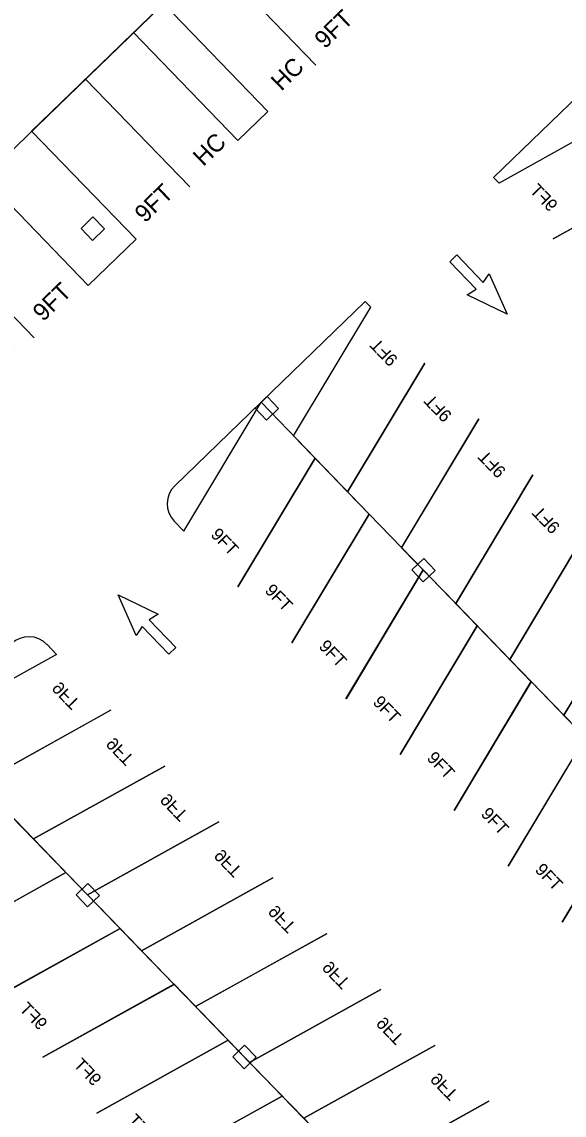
# Model space of a CAD drawing. Extents: x 468143 to 491361, y 1438528 to 1468730.
# Drawn here: x 490229.7 to 490294.7, y 1467411.7 to 1467542.8 of the extents above; entities that cross this region are included whole.
import ezdxf

# ---------------------------------------------------------------- set-up
doc = ezdxf.new("R2010")
doc.units = 0
doc.layers.add('Default', color=7, linetype='Continuous')
doc.layers.add('Xreference_dp', color=7, linetype='Continuous')

# ---------------------------------------------------------------- blocks, each defined once
blk = doc.blocks.new('STALL 9FT-75D')
at = {"layer": 'Default'}
for p, q in [((0, 0), (111.8, 0)), ((111.8, 0), (167.7, -208.6))]:
    blk.add_line(p, q, dxfattribs=at)
blk.add_lwpolyline([(55.9, -208.6), (0, 0)], dxfattribs=at)
blk.add_text('9FT', height=18, dxfattribs=at).set_placement((86.4, -185.9))
blk = doc.blocks.new('arrow-thru')
at = {"layer": 'Default'}
blk.add_lwpolyline([(14.99997, 0), (28.999942, 0), (28.999942, 54.99989), (43.999912, 51.999896), (21.999956, 111.999776), (0, 51.999896), (14.99997, 54.99989)], close=True, dxfattribs=at)
blk = doc.blocks.new('STALL 9FT')
at = {"layer": 'Default'}
for points in [[(0, 0), (0, 216)], [(108, 216), (108, 0)]]:
    blk.add_lwpolyline(points, dxfattribs=at)
blk.add_text('9FT', height=25, dxfattribs=at).set_placement((24.7, 7.1))
blk = doc.blocks.new('STALL HC')
at = {"layer": 'Default'}
blk.add_lwpolyline([(0, 0), (0, 216), (96, 216), (96, 0)], dxfattribs=at)
blk.add_text('HC', height=25, dxfattribs=at).set_placement((33.6, 7.1))
blk = doc.blocks.new('Col 24x24')
at = {"layer": 'Default'}
blk.add_lwpolyline([(-11.999976, -11.999976), (-11.999976, 11.999976), (11.999976, 11.999976), (11.999976, -11.999976), (-11.999976, -11.999976)], dxfattribs=at)
blk.add_lwpolyline([(-11.999976, -11.999976), (11.999976, -11.999976), (11.999976, 11.999976), (-11.999976, 11.999976)], close=True, dxfattribs=at)

msp = doc.modelspace()

# ---------------------------------------------------------------- linework, layer by layer
at = {"layer": 'Xreference_dp'}
for p, q in [((490265.37, 1467563.03), (490230.88, 1467529.65)), ((490265.37, 1467563.03), (490230.88, 1467529.65)), ((490298.74, 1467536.2), (490286.25, 1467524.11)), ((490298.74, 1467536.2), (490286.25, 1467524.11)), ((490255.61, 1467528.54), (490259.2, 1467532.01)), ((490255.61, 1467528.54), (490259.2, 1467532.01)), ((490286.91, 1467523.43), (490286.25, 1467524.11)), ((490286.91, 1467523.43), (490286.25, 1467524.11)), ((490237.64, 1467511.15), (490243.39, 1467516.71)), ((490237.64, 1467511.15), (490243.39, 1467516.71)), ((490258.38, 1467497.15), (490270.87, 1467509.24)), ((490258.38, 1467497.15), (490270.87, 1467509.24)), ((490271.53, 1467508.56), (490270.87, 1467509.24)), ((490271.53, 1467508.56), (490270.87, 1467509.24))]:
    msp.add_line(p, q, dxfattribs=at)
for points in [[(490163.78, 1467464.71), (490266.02, 1467563.64), (490277.14, 1467552.15), (490385.5, 1467657)], [(490163.78, 1467464.71), (490266.02, 1467563.64), (490277.14, 1467552.15), (490385.5, 1467657)], [(490248.04, 1467487.14), (490258.38, 1467497.15)], [(490248.04, 1467487.14), (490258.38, 1467497.15)], [(490249.12, 1467481.71), (490247.97, 1467482.9)], [(490249.12, 1467481.71), (490247.97, 1467482.9)], [(490233.87, 1467466.94), (490232.72, 1467468.14)], [(490233.87, 1467466.94), (490232.72, 1467468.14)]]:
    msp.add_lwpolyline(points, dxfattribs=at)
for centre, start, end in [((490250.12, 1467484.99), 134.0571, 224.0571), ((490250.12, 1467484.99), 134.0571, 224.0571), ((490230.56, 1467466.05), 44.0571, 134.0571), ((490230.56, 1467466.05), 44.0571, 134.0571)]:
    msp.add_arc(centre, 3, start, end, dxfattribs=at)

# ---------------------------------------------------------------- block references
for name, p, xscale, yscale, rotation in [('STALL 9FT', (490264.95, 1467537.58), 0.0833307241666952, 0.08333072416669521, 44.05706724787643), ('STALL 9FT', (490264.95, 1467537.58), 0.0833307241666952, 0.08333072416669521, 44.05706724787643), ('STALL HC', (490259.2, 1467532.01), 0.08333072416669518, 0.0833307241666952, 44.069997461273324), ('STALL HC', (490259.2, 1467532.01), 0.08333072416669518, 0.0833307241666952, 44.069997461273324), ('STALL HC', (490249.86, 1467522.97), 0.08333072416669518, 0.0833307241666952, 44.069997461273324), ('STALL HC', (490249.86, 1467522.97), 0.08333072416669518, 0.0833307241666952, 44.069997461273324), ('STALL 9FT', (490243.39, 1467516.71), 0.0833307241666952, 0.08333072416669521, 44.05706724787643), ('STALL 9FT', (490243.39, 1467516.71), 0.0833307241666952, 0.08333072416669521, 44.05706724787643), ('STALL 9FT-75D', (490309.12, 1467525.48), 0.08333072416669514, -0.08333072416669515, 134.0570672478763), ('STALL 9FT-75D', (490309.12, 1467525.48), 0.08333072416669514, -0.08333072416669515, 134.0570672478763), ('STALL 9FT-75D', (490315.6, 1467518.78), 0.08333072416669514, -0.08333072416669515, 134.0570672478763), ('STALL 9FT-75D', (490315.6, 1467518.78), 0.08333072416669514, -0.08333072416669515, 134.0570672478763), ('STALL 9FT', (490231.18, 1467504.89), 0.0833307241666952, 0.08333072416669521, 44.05706724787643), ('STALL 9FT', (490231.18, 1467504.89), 0.0833307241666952, 0.08333072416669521, 44.05706724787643), ('Col 24x24', (490238.21, 1467517.98), 0.0833307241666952, 0.0833307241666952, 44.062944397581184), ('Col 24x24', (490238.21, 1467517.98), 0.0833307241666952, 0.0833307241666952, 44.062944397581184), ('STALL 9FT', (490224.71, 1467498.64), 0.0833307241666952, 0.08333072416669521, 44.05706724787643), ('STALL 9FT', (490224.71, 1467498.64), 0.0833307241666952, 0.08333072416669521, 44.05706724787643), ('arrow-thru', (490280.09, 1467513.13), 0.08333072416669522, -0.08333072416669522, 44.057067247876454), ('arrow-thru', (490280.09, 1467513.13), 0.08333072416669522, -0.08333072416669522, 44.057067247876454), ('STALL 9FT-75D', (490268.75, 1467486.42), 0.0833307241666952, 0.08333072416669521, 134.05706724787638), ('STALL 9FT-75D', (490268.75, 1467486.42), 0.0833307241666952, 0.08333072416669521, 134.05706724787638), ('STALL 9FT-75D', (490275.23, 1467479.73), 0.0833307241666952, 0.08333072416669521, 134.05706724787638), ('STALL 9FT-75D', (490275.23, 1467479.73), 0.0833307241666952, 0.08333072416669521, 134.05706724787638), ('STALL 9FT-75D', (490258.38, 1467497.15), 0.08333072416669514, 0.08333072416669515, -45.942932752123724), ('STALL 9FT-75D', (490258.38, 1467497.15), 0.08333072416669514, 0.08333072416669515, -45.942932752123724), ('Col 24x24', (490259.07, 1467496.43), 0.0833307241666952, 0.0833307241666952, 44.062944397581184), ('Col 24x24', (490259.07, 1467496.43), 0.0833307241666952, 0.0833307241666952, 44.062944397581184), ('STALL 9FT-75D', (490281.71, 1467473.03), 0.0833307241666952, 0.08333072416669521, 134.05706724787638), ('STALL 9FT-75D', (490281.71, 1467473.03), 0.0833307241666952, 0.08333072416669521, 134.05706724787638), ('STALL 9FT-75D', (490264.86, 1467490.45), 0.08333072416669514, 0.08333072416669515, -45.942932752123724), ('STALL 9FT-75D', (490264.86, 1467490.45), 0.08333072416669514, 0.08333072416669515, -45.942932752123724), ('STALL 9FT-75D', (490288.19, 1467466.34), 0.0833307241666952, 0.08333072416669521, 134.05706724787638), ('STALL 9FT-75D', (490288.19, 1467466.34), 0.0833307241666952, 0.08333072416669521, 134.05706724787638), ('STALL 9FT-75D', (490271.34, 1467483.75), 0.08333072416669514, 0.08333072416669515, -45.942932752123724), ('STALL 9FT-75D', (490271.34, 1467483.75), 0.08333072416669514, 0.08333072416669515, -45.942932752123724), ('STALL 9FT-75D', (490294.67, 1467459.64), 0.0833307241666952, 0.08333072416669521, 134.05706724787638), ('STALL 9FT-75D', (490294.67, 1467459.64), 0.0833307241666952, 0.08333072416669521, 134.05706724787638), ('Col 24x24', (490277.85, 1467477.03), 0.0833307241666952, 0.0833307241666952, 44.062944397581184), ('Col 24x24', (490277.85, 1467477.03), 0.0833307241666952, 0.0833307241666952, 44.062944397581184), ('STALL 9FT-75D', (490277.81, 1467477.06), 0.08333072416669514, 0.08333072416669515, -45.942932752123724), ('STALL 9FT-75D', (490277.81, 1467477.06), 0.08333072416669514, 0.08333072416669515, -45.942932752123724), ('arrow-thru', (490249.06, 1467468.65), 0.0833307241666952, -0.08333072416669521, -135.9429327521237), ('arrow-thru', (490249.06, 1467468.65), 0.0833307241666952, -0.08333072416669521, -135.9429327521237), ('STALL 9FT-75D', (490301.15, 1467452.94), 0.0833307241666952, 0.08333072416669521, 134.05706724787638), ('STALL 9FT-75D', (490301.15, 1467452.94), 0.0833307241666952, 0.08333072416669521, 134.05706724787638), ('STALL 9FT-75D', (490218.14, 1467458.2), 0.0833307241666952, -0.0833307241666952, -45.94293275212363), ('STALL 9FT-75D', (490218.14, 1467458.2), 0.0833307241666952, -0.0833307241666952, -45.94293275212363), ('STALL 9FT-75D', (490284.29, 1467470.36), 0.08333072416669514, 0.08333072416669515, -45.942932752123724), ('STALL 9FT-75D', (490284.29, 1467470.36), 0.08333072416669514, 0.08333072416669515, -45.942932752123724), ('STALL 9FT-75D', (490224.62, 1467451.51), 0.0833307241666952, -0.0833307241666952, -45.94293275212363), ('STALL 9FT-75D', (490224.62, 1467451.51), 0.0833307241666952, -0.0833307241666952, -45.94293275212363), ('STALL 9FT-75D', (490290.77, 1467463.67), 0.08333072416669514, 0.08333072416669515, -45.942932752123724), ('STALL 9FT-75D', (490290.77, 1467463.67), 0.08333072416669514, 0.08333072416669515, -45.942932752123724), ('STALL 9FT-75D', (490231.1, 1467444.81), 0.0833307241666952, -0.0833307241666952, -45.94293275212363), ('STALL 9FT-75D', (490231.1, 1467444.81), 0.0833307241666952, -0.0833307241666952, -45.94293275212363), ('STALL 9FT-75D', (490297.25, 1467456.97), 0.08333072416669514, 0.08333072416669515, -45.942932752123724), ('STALL 9FT-75D', (490297.25, 1467456.97), 0.08333072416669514, 0.08333072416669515, -45.942932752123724), ('STALL 9FT-75D', (490234.99, 1467440.78), 0.08333072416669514, -0.08333072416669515, 134.0570672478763), ('STALL 9FT-75D', (490234.99, 1467440.78), 0.08333072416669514, -0.08333072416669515, 134.0570672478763), ('STALL 9FT-75D', (490237.57, 1467438.12), 0.0833307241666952, -0.0833307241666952, -45.94293275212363), ('STALL 9FT-75D', (490237.57, 1467438.12), 0.0833307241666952, -0.0833307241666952, -45.94293275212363), ('STALL 9FT-75D', (490303.73, 1467450.28), 0.08333072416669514, 0.08333072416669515, -45.942932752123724), ('STALL 9FT-75D', (490303.73, 1467450.28), 0.08333072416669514, 0.08333072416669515, -45.942932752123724), ('STALL 9FT-75D', (490241.47, 1467434.09), 0.08333072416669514, -0.08333072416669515, 134.0570672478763), ('STALL 9FT-75D', (490241.47, 1467434.09), 0.08333072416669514, -0.08333072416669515, 134.0570672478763), ('STALL 9FT-75D', (490244.05, 1467431.42), 0.0833307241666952, -0.0833307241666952, -45.94293275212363), ('STALL 9FT-75D', (490244.05, 1467431.42), 0.0833307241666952, -0.0833307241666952, -45.94293275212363), ('Col 24x24', (490237.61, 1467438.08), 0.0833307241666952, 0.0833307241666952, 44.062944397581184), ('Col 24x24', (490237.61, 1467438.08), 0.0833307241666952, 0.0833307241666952, 44.062944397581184), ('STALL 9FT-75D', (490247.95, 1467427.39), 0.08333072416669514, -0.08333072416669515, 134.0570672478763), ('STALL 9FT-75D', (490247.95, 1467427.39), 0.08333072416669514, -0.08333072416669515, 134.0570672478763), ('STALL 9FT-75D', (490250.53, 1467424.72), 0.0833307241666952, -0.0833307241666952, -45.94293275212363), ('STALL 9FT-75D', (490250.53, 1467424.72), 0.0833307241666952, -0.0833307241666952, -45.94293275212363), ('STALL 9FT-75D', (490254.43, 1467420.7), 0.08333072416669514, -0.08333072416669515, 134.0570672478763), ('STALL 9FT-75D', (490254.43, 1467420.7), 0.08333072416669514, -0.08333072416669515, 134.0570672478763), ('STALL 9FT-75D', (490257.01, 1467418.03), 0.0833307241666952, -0.0833307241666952, -45.94293275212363), ('STALL 9FT-75D', (490257.01, 1467418.03), 0.0833307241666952, -0.0833307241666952, -45.94293275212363), ('STALL 9FT-75D', (490260.91, 1467414), 0.08333072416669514, -0.08333072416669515, 134.0570672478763), ('STALL 9FT-75D', (490260.91, 1467414), 0.08333072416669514, -0.08333072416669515, 134.0570672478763), ('STALL 9FT-75D', (490263.49, 1467411.33), 0.0833307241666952, -0.0833307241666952, -45.94293275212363), ('STALL 9FT-75D', (490263.49, 1467411.33), 0.0833307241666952, -0.0833307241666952, -45.94293275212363), ('Col 24x24', (490256.39, 1467418.68), 0.0833307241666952, 0.0833307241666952, 44.062944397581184), ('Col 24x24', (490256.39, 1467418.68), 0.0833307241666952, 0.0833307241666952, 44.062944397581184), ('STALL 9FT-75D', (490267.39, 1467407.31), 0.08333072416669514, -0.08333072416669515, 134.0570672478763), ('STALL 9FT-75D', (490267.39, 1467407.31), 0.08333072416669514, -0.08333072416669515, 134.0570672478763), ('STALL 9FT-75D', (490269.97, 1467404.64), 0.0833307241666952, -0.0833307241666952, -45.94293275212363), ('STALL 9FT-75D', (490269.97, 1467404.64), 0.0833307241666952, -0.0833307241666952, -45.94293275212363)]:
    msp.add_blockref(name, p, dxfattribs=dict(at, xscale=xscale, yscale=yscale, rotation=rotation))

doc.saveas('drawing.dxf')
